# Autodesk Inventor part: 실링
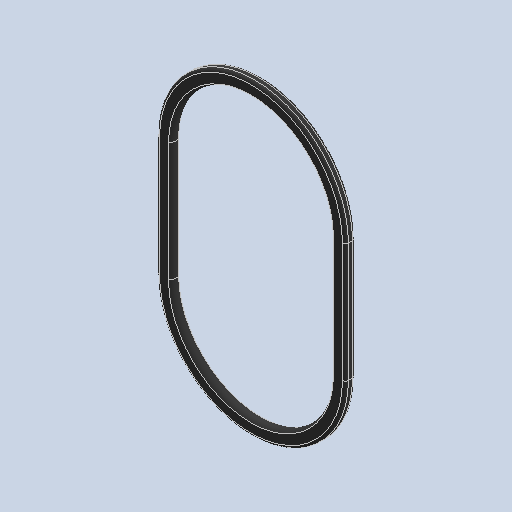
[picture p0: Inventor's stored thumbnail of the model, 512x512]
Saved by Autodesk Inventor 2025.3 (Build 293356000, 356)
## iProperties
Created: 2025-10
Part Number: 실링
Material: 고무
Document SubType Name: Modeling
Designer: PC-13
Density: 0.93 g/cm^3
Appearance: 기본값
Author: jhkim
Sending System: Autodesk Inventor 2026
Preprocessor: ST-DEVELOPER v20.1
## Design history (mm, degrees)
feature "솔리드3"
node "솔리드1"
